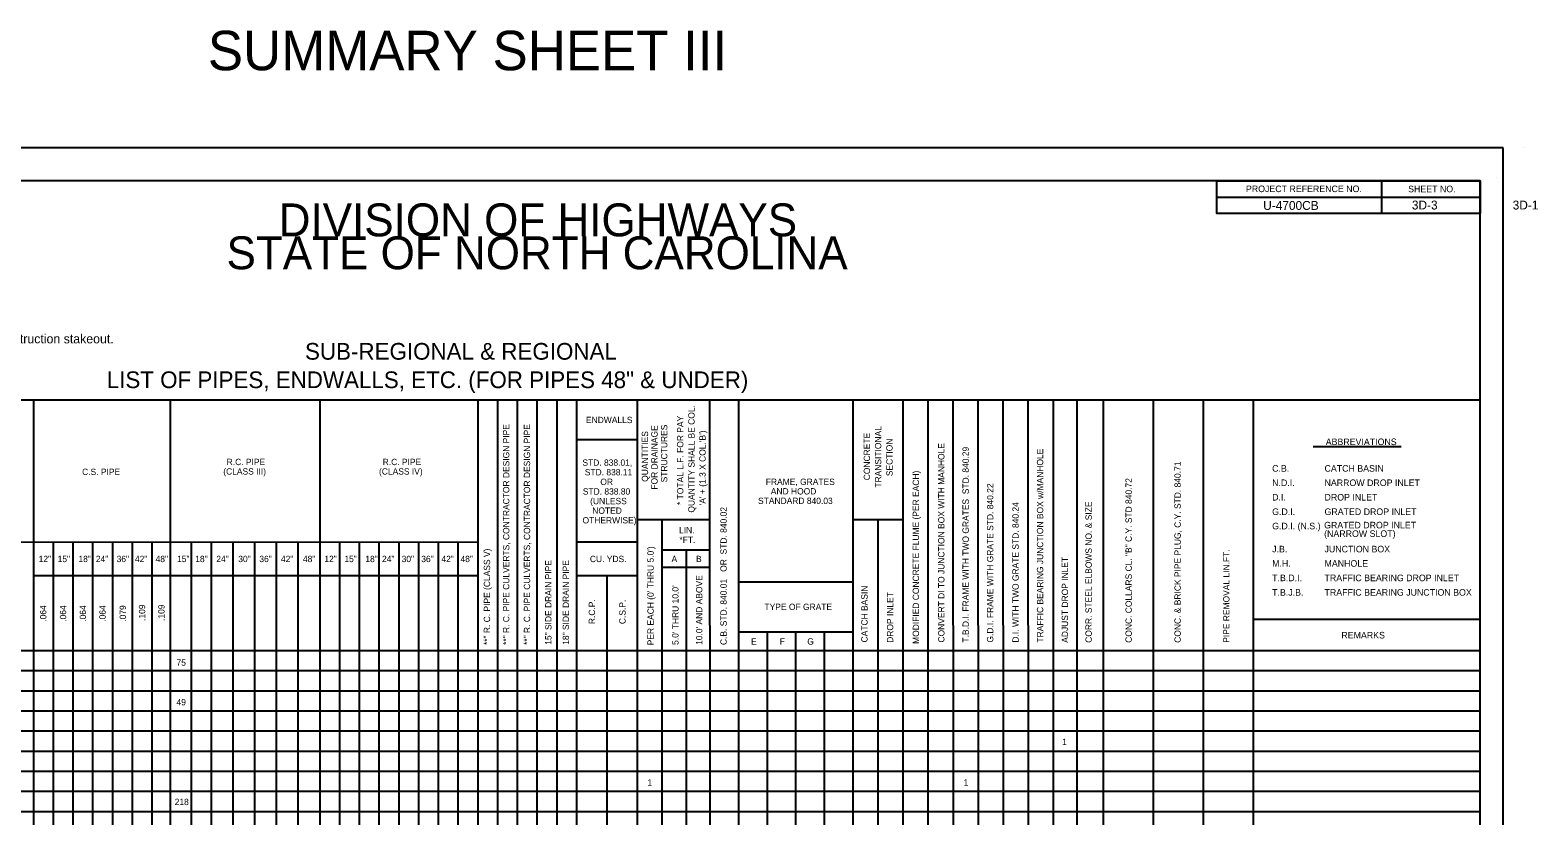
# Model space of a CAD drawing. Extents: x 809447 to 814738, y 647528 to 651206.
# Drawn here: x 813593 to 814738, y 650609 to 651206 of the extents above; entities that cross this region are included whole.
import ezdxf

# ---------------------------------------------------------------- set-up
doc = ezdxf.new("R2010")
doc.units = 0
doc.layers.add('Default', color=7, linetype='Continuous')
doc.layers.add('Old_Level_44', color=7, linetype='Continuous')

msp = doc.modelspace()

# ---------------------------------------------------------------- linework, layer by layer
at = {"layer": 'Default'}
for p, q in [((814728.1, 651116.9), (814728.1, 651116.9)), ((814728.1, 651116.9), (814728.1, 651116.9)), ((814728.1, 651116.9), (814728.1, 651116.9)), ((814619.6, 651091.9), (814619.6, 651066.9)), ((814707.1, 651094.5), (814707.1, 651094.5)), ((814707.1, 651094.5), (814707.1, 651094.5)), ((814707.1, 651094.5), (814707.1, 651094.5)), ((814494.5, 651079.4), (814694.6, 651079.4)), ((814694.6, 650925.1), (813194.6, 650925)), ((813595.9, 650154.3), (813595.9, 650925)), ((813699.9, 650154.3), (813699.8, 650925)), ((813813.4, 650154.3), (813813.4, 650925.1)), ((813933.4, 650154.3), (813933.4, 650925.1)), ((813948.4, 650154.3), (813948.4, 650925.1)), ((813963.4, 650154.3), (813963.4, 650925.1)), ((813978.4, 650154.3), (813978.4, 650925.1)), ((813993.4, 650154.3), (813993.4, 650925.1)), ((814008.4, 650154.3), (814008.4, 650925.1)), ((814008.4, 650154.3), (814008.4, 650925.1)), ((814008.4, 650154.3), (814008.4, 650925.1)), ((814054.7, 650154.3), (814054.6, 650925)), ((814109.7, 650154.3), (814109.6, 650925)), ((814109.7, 650154.3), (814109.6, 650925)), ((814131.5, 650154.3), (814131.5, 650925)), ((814218.5, 650154.3), (814218.4, 650925)), ((814256.5, 650154.3), (814256.4, 650925)), ((814275.5, 650154.3), (814275.4, 650925)), ((814294.5, 650154.3), (814294.4, 650925)), ((814313.5, 650154.3), (814313.4, 650925)), ((814332.5, 650154.3), (814332.4, 650925)), ((814351.5, 650154.3), (814351.4, 650925)), ((814370.5, 650154.3), (814370.4, 650925)), ((814388.6, 650154.3), (814388.5, 650925.1)), ((814408.5, 650154.3), (814408.4, 650925)), ((814408.5, 650154.3), (814408.4, 650925)), ((814446.5, 650154.3), (814446.4, 650925)), ((814446.5, 650154.3), (814446.4, 650925)), ((814484.5, 650154.3), (814484.4, 650925)), ((814484.5, 650154.3), (814484.4, 650925)), ((814522.5, 650154.3), (814522.4, 650925)), ((814522.5, 650154.3), (814522.4, 650925)), ((814054.6, 650895.1), (814008.4, 650895.1)), ((814634.7, 650889.6), (814567.7, 650889.6)), ((814108.4, 650834.3), (814054.6, 650834.3)), ((814073.3, 650154.3), (814073.2, 650834.3)), ((814256.4, 650834.3), (814218.4, 650834.3)), ((814237.5, 650154.3), (814237.4, 650834.3)), ((813933.4, 650817.2), (813415.9, 650817.1)), ((813610.9, 650154.3), (813610.9, 650817.1)), ((813625.9, 650154.3), (813625.9, 650817.2)), ((813640.9, 650154.3), (813640.9, 650817.1)), ((813655.9, 650154.3), (813655.9, 650817.2)), ((813670.9, 650154.3), (813670.9, 650817.1)), ((813685.9, 650154.3), (813685.9, 650817.2)), ((813715.9, 650154.3), (813715.9, 650817.2)), ((813730.9, 650154.3), (813730.9, 650817.2)), ((813747.4, 650154.3), (813747.4, 650817.2)), ((813763.9, 650154.3), (813763.9, 650817.2)), ((813780.4, 650154.3), (813780.4, 650817.2)), ((813796.9, 650154.3), (813796.9, 650817.2)), ((813813.4, 650154.3), (813813.4, 650817.2)), ((813828.4, 650154.3), (813828.4, 650817.2)), ((813843.4, 650154.3), (813843.4, 650817.2)), ((813858.4, 650154.3), (813858.4, 650817.2)), ((813873.4, 650154.3), (813873.4, 650817.2)), ((813888.4, 650154.3), (813888.4, 650817.2)), ((813903.4, 650154.3), (813903.4, 650817.2)), ((813918.4, 650154.3), (813918.4, 650817.2)), ((813933.4, 650154.3), (813933.4, 650817.2)), ((814054.6, 650817.2), (814008.4, 650817.2)), ((814109.6, 650811.1), (814073.2, 650811.1)), ((814091.8, 650154.3), (814091.8, 650811.1)), ((814109.6, 650797.9), (814073.2, 650797.9)), ((813933.4, 650791.8), (813595.9, 650791.8)), ((813595.9, 650154.3), (813595.9, 650791.8)), ((814054.6, 650791.8), (814008.4, 650791.8)), ((814031.6, 650154.3), (814031.5, 650791.8)), ((814218.4, 650786.8), (814131.5, 650786.8)), ((814694.6, 650758.5), (814522.4, 650758.5)), ((814218.4, 650749), (814131.5, 650749)), ((814153.2, 650154.3), (814153.2, 650749)), ((814175, 650154.3), (814174.9, 650749)), ((814196.7, 650154.3), (814196.7, 650749)), ((814694.6, 650734.7), (813194.6, 650734.7)), ((814694.6, 650719.4), (813194.6, 650719.4)), ((814694.6, 650704.1), (813194.6, 650704.1)), ((814694.6, 650688.9), (813194.6, 650688.9)), ((814694.6, 650673.6), (813194.6, 650673.6)), ((814694.6, 650658.3), (813194.6, 650658.3)), ((814694.6, 650643), (813194.6, 650643)), ((814694.6, 650627.8), (813194.6, 650627.8)), ((814694.6, 650612.5), (813194.6, 650612.5))]:
    msp.add_line(p, q, dxfattribs=at)
for points in [[(814712.1, 651116.9), (813028.1, 651116.9), (813028.1, 650016.9), (814712.1, 650016.9)], [(814694.6, 651091.9), (813194.6, 651091.9), (813194.6, 650041.9), (814694.6, 650041.9)], [(814494.5, 651091.9), (814694.6, 651091.9), (814694.6, 651066.9), (814494.5, 651066.9)]]:
    msp.add_lwpolyline(points, close=True, dxfattribs=at)

# ---------------------------------------------------------------- texts
for s, height, rotation, p in [('PROJECT REFERENCE NO.', 5, 360, (814516.7, 651083.2)), ('SHEET NO.', 5, 360, (814639.9, 651083.1)), ('DIVISION OF HIGHWAYS', 25, 360, (813782, 651049.6)), ('U-4700CB', 6.75, 360, (814529.8, 651069.7)), ('3D-3', 6.75, 360, (814642.7, 651070)), ('3D-1', 6.75, 360, (814719.3, 651070)), ('STATE OF NORTH CAROLINA', 25, 360, (813742.4, 651024.6)), ('QUANTITY SHALL BE COL.', 4.8, 90, (814097.9, 650839.7)), ('* TOTAL L.F. FOR PAY', 4.8, 90, (814089.4, 650845.5)), ('**" R. C. PIPE CULVERTS, CONTRACTOR DESIGN PIPE', 4.8, 90, (813957.2, 650739.2)), ('**" R. C. PIPE CULVERTS, CONTRACTOR DESIGN PIPE', 4.8, 90, (813973, 650739.2)), ('QUANTITIES', 4.8, 90, (814062.6, 650863.1)), ('FOR DRAINAGE', 4.8, 90, (814069.8, 650857.2)), ('STRUCTURES', 4.8, 90, (814077.2, 650862.7)), ("'A' + (1.3 X COL.'B')", 4.8, 90, (814106.3, 650845.3)), ('CONCRETE', 4.8, 90, (814231.2, 650864.3)), ('TRANSITIONAL', 4.8, 90, (814239.7, 650858.7)), ('SECTION', 4.8, 90, (814248.3, 650867.4)), ('CONVERT DI TO JUNCTION BOX WITH MANHOLE', 4.8, 90, (814287.7, 650741)), ('T.B.D.I. FRAME WITH TWO GRATES  STD. 840.29', 4.8, 90, (814306.2, 650741)), ('TRAFFIC BEARING JUNCTION BOX w/MANHOLE', 4.8, 90, (814362.7, 650741)), ('CONC. & BRICK PIPE PLUG, C.Y. STD. 840.71', 4.8, 90, (814467.2, 650740.8)), ('MODIFIED CONCRETE FLUME (PER EACH)', 4.8, 90, (814268.4, 650740)), ('G.D.I. FRAME WITH GRATE STD. 840.22', 4.8, 90, (814324.8, 650741)), ('CONC. COLLARS CL. "B" C.Y. STD 840.72', 4.8, 90, (814430, 650740.8)), ('C.B. STD. 840.01   OR  STD. 840.02', 4.8, 90, (814122.3, 650739.1)), ('D.I. WITH TWO GRATE STD. 840.24', 4.8, 90, (814344.1, 650741)), ('CORR. STEEL ELBOWS NO. & SIZE', 4.8, 90, (814399.6, 650740.8)), ('GRATED DROP INLET', 5, 0.0274, (814576.1, 650827.7)), ('(NARROW SLOT)', 5, 0.0274, (814576.1, 650821.2)), ('**" R. C. PIPE (CLASS V)', 4.8, 90, (813942.6, 650739.1)), ("PER EACH (0' THRU 5.0')", 4.799, 90.0369, (814066.9, 650738.9)), ('ADJUST DROP INLET', 4.8, 90, (814381.6, 650740.8)), ('PIPE REMOVAL LIN.FT.', 4.8, 90, (814504.2, 650740.8)), ('15" SIDE DRAIN PIPE', 4.8, 90, (813989.2, 650739.3)), ('18" SIDE DRAIN PIPE', 4.8, 90, (814002.5, 650739.3)), ("5.0' THRU 10.0'", 4.8, 90, (814085.7, 650739.2)), ("10.0' AND ABOVE", 4.8, 90, (814103.8, 650739.2)), ('CATCH BASIN', 4.8, 90, (814229.3, 650741.1)), ('R.C.P.', 4.8, 90, (814022.3, 650755)), ('C.S.P.', 4.8, 90, (814045.5, 650755)), ('DROP INLET', 4.8, 90, (814248.8, 650740.8)), ('.064', 4.8, 90, (813605.5, 650756.8)), ('.064', 4.8, 90, (813620.6, 650756.8)), ('.064', 4.8, 90, (813635.7, 650756.8)), ('.064', 4.8, 90, (813650.6, 650756.8)), ('.079', 4.8, 90, (813666, 650756.8)), ('.109', 4.8, 90, (813680.6, 650757.4)), ('.109', 4.8, 90, (813695.3, 650757.4))]:
    msp.add_text(s, height=height, rotation=rotation, dxfattribs=at).set_placement(p)
for s, height, p in [('NOTE: Invert Elevations are for Bid Purposes only and shall not be used for project construction stakeout.', 7, (813219.1, 650968.3)), ('SUB-REGIONAL & REGIONAL', 12.7, (813802, 650955.9)), ('LIST OF PIPES, ENDWALLS, ETC. (FOR PIPES 48" & UNDER)', 12.7, (813651.4, 650934.3)), ('ENDWALLS', 4.8, (814015.4, 650907.7)), ('ABBREVIATIONS', 5, (814577.3, 650891)), ('C.S. PIPE', 4.8, (813632.7, 650868.3)), ('(CLASS III)', 4.8, (813739.9, 650868.6)), ('R.C. PIPE', 4.8, (813742.5, 650875.8)), ('(CLASS IV)', 4.8, (813858.2, 650868.6)), ('R.C. PIPE', 4.8, (813861, 650875.8)), ('STD. 838.01,', 4.8, (814012.7, 650875.3)), ('STD. 838.11', 4.8, (814014.5, 650868)), ('C.B.', 5, (814536.6, 650870.8)), ('CATCH BASIN', 5, (814576.4, 650870.8)), ('OR', 4.8, (814026.3, 650860.7)), ('FRAME, GRATES', 4.8, (814152, 650860.7)), ('N.D.I.', 5, (814536.6, 650859.9)), ('NARROW DROP INLET', 5, (814576.4, 650859.9)), ('STD. 838.80', 4.8, (814013, 650853.4)), ('(UNLESS', 4.8, (814018.6, 650846.1)), ('STANDARD 840.03', 4.8, (814146.1, 650846.3)), ('AND HOOD', 4.8, (814155.8, 650853.5)), ('D.I.', 5, (814536.6, 650848.9)), ('DROP INLET', 5, (814576.4, 650848.9)), ('NOTED', 4.8, (814020.2, 650838.8)), ('G.D.I.', 5, (814536.6, 650837.9)), ('GRATED DROP INLET', 5, (814576.4, 650837.9)), ('OTHERWISE)', 4.8, (814012.8, 650831.5)), ('LIN.', 4.8, (814086.1, 650824)), ('G.D.I. (N.S.)', 5, (814536.6, 650827)), ('*FT.', 4.8, (814086.4, 650816.7)), ('12"', 4.8, (813599.7, 650802.1)), ('15"', 4.8, (813614.1, 650802.1)), ('18"', 4.8, (813629.9, 650802.1)), ('24"', 4.8, (813643.1, 650802.1)), ('36"', 4.8, (813658.9, 650802.1)), ('42"', 4.8, (813672.8, 650802.1)), ('48"', 4.8, (813688.5, 650802.1)), ('15"', 4.8, (813704.8, 650802.1)), ('18"', 4.8, (813718.6, 650802.1)), ('24"', 4.8, (813734.6, 650802.1)), ('30"', 4.8, (813751.3, 650802.1)), ('36"', 4.8, (813767.3, 650802.1)), ('42"', 4.8, (813783.7, 650802.1)), ('48"', 4.8, (813800.4, 650802.1)), ('12"', 4.8, (813816.7, 650802.1)), ('15"', 4.8, (813831.9, 650802.1)), ('18"', 4.8, (813847.8, 650802.1)), ('24"', 4.8, (813860.5, 650802.1)), ('30"', 4.8, (813875.4, 650802.1)), ('36"', 4.8, (813890.3, 650802.1)), ('42"', 4.8, (813905.6, 650802.1)), ('48"', 4.8, (813920.1, 650802.1)), ('CU. YDS.', 4.8, (814018.4, 650802.1)), ('A', 4.8, (814080.4, 650802.1)), ('B', 4.8, (814099, 650802.1)), ('J.B.', 5, (814536.6, 650809.5)), ('JUNCTION BOX', 5, (814576.4, 650809.5)), ('T.B.D.I.', 5, (814536.6, 650787.6)), ('M.H.', 5, (814536.6, 650798.6)), ('TRAFFIC BEARING DROP INLET', 5, (814576.4, 650787.6)), ('MANHOLE', 5, (814576.4, 650798.6)), ('T.B.J.B.', 5, (814536.6, 650776.6)), ('TRAFFIC BEARING JUNCTION BOX', 5, (814576.4, 650776.6)), ('TYPE OF GRATE', 4.8, (814151, 650765.7)), ('REMARKS', 5, (814589.2, 650744.1)), ('E', 4.8, (814140.8, 650739.4)), ('F', 4.8, (814162.6, 650739.4)), ('G', 4.8, (814183.5, 650739.4)), ('75', 4.8, (813704.4, 650723.4)), ('49', 4.8, (813704.4, 650693.3)), ('1', 4.8, (814377.1, 650663.1)), ('1', 4.8, (814062.1, 650632.3)), ('1', 4.8, (814302.2, 650632.3)), ('218', 4.8, (813703, 650617.5))]:
    msp.add_text(s, height=height, dxfattribs=at).set_placement(p)
at = {"layer": 'Old_Level_44'}
msp.add_text('SUMMARY SHEET III', height=30, rotation=360, dxfattribs=at).set_placement((813728.2, 651175.8))

doc.saveas('drawing.dxf')
